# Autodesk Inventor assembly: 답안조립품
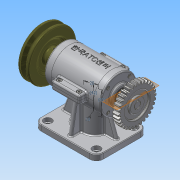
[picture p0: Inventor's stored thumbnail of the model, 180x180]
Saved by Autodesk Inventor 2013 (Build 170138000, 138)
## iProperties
Created: 2015-09
Part Number: 답안조립품
Document SubType Name: Assembly
Designer: Administrator
Author: Administrator
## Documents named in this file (17)
- C:\Users\Administrator\Desktop\350908V1028\답안조립품.iam
- C:\Users\Administrator\Desktop\350908V1028\본체.ipt
- C:\Users\Administrator\Desktop\350908V1028\M3x0.5x8.ipt
- C:\Users\Administrator\Desktop\350908V1028\M4x0.5x14.ipt
- C:\Users\Administrator\Desktop\350908V1028\V-벨트풀리.ipt
- C:\Users\Administrator\Desktop\350908V1028\가변스프링.ipt
- C:\Users\Administrator\Desktop\350908V1028\뒤커버.ipt
- C:\Users\Administrator\Desktop\350908V1028\멈춤나사.ipt
- C:\Users\Administrator\Desktop\350908V1028\베어링 6201.ipt
- C:\Users\Administrator\Desktop\350908V1028\베어링 6202.ipt
- C:\Users\Administrator\Desktop\350908V1028\본체 커버.ipt
- C:\Users\Administrator\Desktop\350908V1028\스퍼기어.ipt
- C:\Users\Administrator\Desktop\350908V1028\슬라이드.ipt
- C:\Users\Administrator\Desktop\350908V1028\앞커버.ipt
- C:\Users\Administrator\Desktop\350908V1028\오일실.ipt
- C:\Users\Administrator\Desktop\350908V1028\키4x4.ipt
- C:\Users\Administrator\Desktop\350908V1028\편심축.ipt
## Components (14 placed, 4 different names)
1. M4x0.5x14:1
2. V-벨트풀리:1 — 플러쉬:1, 각도:1
3. M3x0.5x8:2
4. M3x0.5x8:1
5. M4x0.5x14:2
6. M4x0.5x14:3
7. M4x0.5x14:4
8. 가변스프링:1
9. M3x0.5x8:3
10. M3x0.5x8:4
11. M3x0.5x8:5
12. M3x0.5x8:6
13. M3x0.5x8:7
14. M3x0.5x8:8
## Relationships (2: Flush 1, Angle 1)
- 플러쉬:1 [Flush]: V-벨트풀리:1
- 각도:1 [Angle]: V-벨트풀리:1
